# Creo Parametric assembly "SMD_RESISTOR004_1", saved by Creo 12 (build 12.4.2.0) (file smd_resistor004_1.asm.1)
Units: Custom; MM, KILOGRAM, SECS

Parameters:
  PTC_WM_ITERATION = "0"
  PTC_WM_VERSION = "-.0"
  PTC_WM_LIFECYCLE_STATE = "In Work"
  PTC_WM_LIFECYCLE = "MO_CADDocument"
  PTC_WM_CREATED_BY = "Maximilian Roepper (Z0017RMS: MO)"
  PTC_WM_CREATED_ON = "18-Sep-26 11:36:42 AM"
  PTC_WM_MODIFIED_BY = "Maximilian Roepper (Z0017RMS: MO)"
  PTC_WM_MODIFIED_ON = "18-Sep-26 11:36:46 AM"
  PDMLINKNUMBER = "PDM000071454888"
  PTC_WM_NUMBER = "PDM000071454888"

Other parameters: WEIGHT, WEIGHT_FACTOR, WEIGHT_ADD, MC_ERRORS, SUPPLIER

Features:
  1. coordinate system
  2. imported feature
  3. component "BODY005_1"
  4. component "CONTACT020_1"
  5. component "CONTACT021_1"
  6. component "LABEL003_1"
  7. component "PART017_1"

Other named items: DRW_VIEW_ORG, ROUGH-GROB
